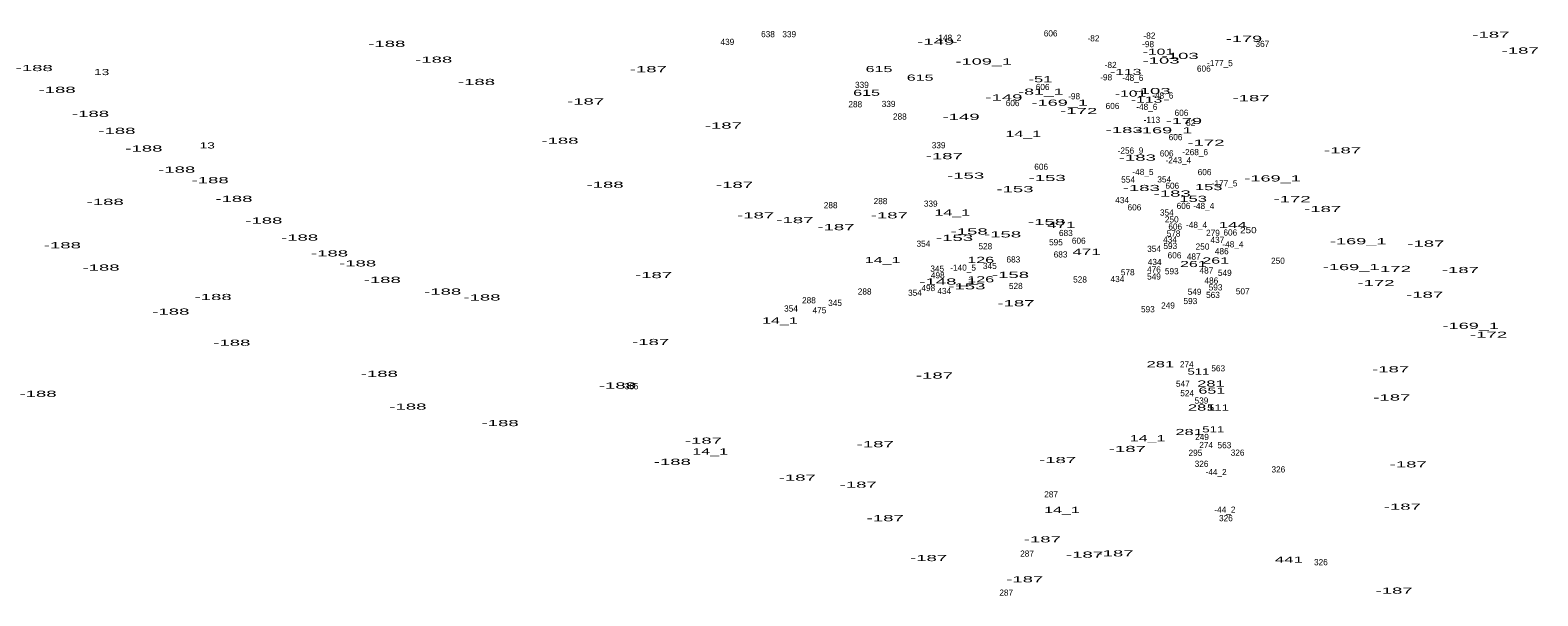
# Model space of a CAD drawing. Extents: x -658595 to -655205, y -1004347 to -1000147.
# Drawn here: x -656433 to -655455, y -1003286 to -1002919 of the extents above; entities that cross this region are included whole.
import ezdxf
from ezdxf.enums import TextEntityAlignment as Align

# ---------------------------------------------------------------- set-up
doc = ezdxf.new("R2010")
doc.units = 0
doc.header["$LTSCALE"] = 1.6
doc.layers.add('24', color=7, linetype='Continuous')

msp = doc.modelspace()

# ---------------------------------------------------------------- texts
at = {"layer": '24'}
for s, p in [('638', (-655954.113, -1002923.98)), ('339', (-655940.333, -1002924.02)), ('606', (-655770.742, -1002923.5)), ('-82', (-655706.665, -1002924.97)), ('439', (-655980.447, -1002929.02)), ('-148_2', (-655837.02, -1002926.35)), ('-82', (-655742.955, -1002926.7)), ('-98', (-655707.53, -1002930.46)), ('367', (-655633.398, -1002930.34)), ('-82', (-655731.815, -1002943.99)), ('-177_5', (-655660.927, -1002942.76)), ('-98', (-655734.7, -1002951.96)), ('-48_6', (-655717.412, -1002952.33)), ('606', (-655671.362, -1002946.34)), ('339', (-655893.173, -1002956.88)), ('606', (-655775.922, -1002958.26)), ('-98', (-655755.53, -1002964.25)), ('-48_6', (-655697.992, -1002963.76)), ('288', (-655897.477, -1002969.41)), ('339', (-655875.863, -1002969.25)), ('606', (-655795.402, -1002968.66)), ('606', (-655730.612, -1002970.55)), ('-48_6', (-655708.362, -1002971.1)), ('288', (-655868.567, -1002977.4)), ('-113', (-655705.071, -1002979.53)), ('606', (-655685.872, -1002974.97)), ('82', (-655679.907, -1002981.41)), ('606', (-655689.712, -1002990.74)), ('339', (-655843.403, -1002996.01)), ('-256_9', (-655718.943, -1002999.45)), ('606', (-655695.472, -1003001.3)), ('-268_6', (-655676.973, -1003000.44)), ('606', (-655776.882, -1003009.93)), ('-243_4', (-655687.891, -1003005.69)), ('554', (-655720.501, -1003018.24)), ('-48_5', (-655710.837, -1003013.33)), ('354', (-655697.071, -1003018.12)), ('606', (-655691.822, -1003022.24)), ('606', (-655670.892, -1003013.4)), ('-177_5', (-655657.887, -1003020.67)), ('288', (-655881.117, -1003032.19)), ('434', (-655724.376, -1003031.54)), ('288', (-655913.447, -1003034.85)), ('339', (-655848.533, -1003033.87)), ('606', (-655716.402, -1003036.26)), ('354', (-655695.361, -1003039.62)), ('606', (-655684.532, -1003035.3)), ('-48_4', (-655671.411, -1003035.34)), ('250', (-655692.171, -1003044.07)), ('606', (-655689.912, -1003048.72)), ('-48_4', (-655676.081, -1003047.62)), ('354', (-655853.261, -1003059.83)), ('528', (-655813.117, -1003061.48)), ('595', (-655767.293, -1003058.89)), ('683', (-655760.873, -1003052.87)), ('606', (-655752.512, -1003057.88)), ('434', (-655693.276, -1003057.12)), ('593', (-655693.123, -1003061.29)), ('578', (-655691.043, -1003053.22)), ('250', (-655672.211, -1003061.68)), ('279', (-655665.438, -1003052.77)), ('437', (-655662.587, -1003057.34)), ('-48_4', (-655652.471, -1003060.19)), ('606', (-655654.192, -1003052.56)), ('683', (-655794.923, -1003070)), ('683', (-655764.303, -1003066.76)), ('354', (-655703.641, -1003063.12)), ('434', (-655703.266, -1003071.67)), ('606', (-655690.392, -1003067.35)), ('487', (-655677.937, -1003068.14)), ('486', (-655659.747, -1003064.67)), ('250', (-655623.281, -1003070.85)), ('345', (-655844.311, -1003075.99)), ('498', (-655843.977, -1003080.29)), ('-140_5', (-655827.524, -1003075.34)), ('345', (-655810.191, -1003074.23)), ('578', (-655720.723, -1003078.34)), ('476', (-655703.713, -1003076.52)), ('549', (-655703.697, -1003081.08)), ('593', (-655692.173, -1003077.66)), ('487', (-655669.687, -1003077.17)), ('549', (-655657.767, -1003078.7)), ('288', (-655891.387, -1003090.79)), ('498', (-655850.107, -1003088.54)), ('434', (-655839.796, -1003090.47)), ('528', (-655793.337, -1003087.21)), ('528', (-655751.667, -1003082.99)), ('434', (-655727.416, -1003082.71)), ('549', (-655677.357, -1003090.97)), ('486', (-655666.467, -1003083.69)), ('593', (-655663.743, -1003088.12)), ('507', (-655646.137, -1003090.67)), ('288', (-655927.527, -1003096.49)), ('345', (-655910.611, -1003098.2)), ('354', (-655858.771, -1003091.6)), ('249', (-655694.597, -1003099.86)), ('593', (-655680.103, -1003096.97)), ('563', (-655665.443, -1003093.02)), ('354', (-655939.181, -1003101.83)), ('475', (-655920.727, -1003102.97)), ('593', (-655707.673, -1003102.29)), ('274', (-655682.397, -1003137.96)), ('563', (-655662.023, -1003140.58)), ('365', (-656042.583, -1003152.2)), ('547', (-655685.007, -1003150.57)), ('524', (-655682.181, -1003156.7)), ('539', (-655672.903, -1003161.5)), ('249', (-655672.537, -1003185.1)), ('295', (-655676.833, -1003195.34)), ('274', (-655669.847, -1003190.28)), ('563', (-655658.033, -1003190.42)), ('326', (-655649.453, -1003195.25)), ('326', (-655672.843, -1003202.48)), ('-44_2', (-655663.401, -1003207.82)), ('326', (-655623.013, -1003206.09)), ('287', (-655770.453, -1003222.25)), ('-44_2', (-655657.691, -1003232.2)), ('326', (-655657.053, -1003237.67)), ('287', (-655786.043, -1003260.68)), ('326', (-655595.433, -1003266.21)), ('287', (-655799.553, -1003285.98))]:
    msp.add_text(s, height=4, dxfattribs=at).set_placement(p, align=Align.CENTER)
for s, width, p in [('-187', 2.25, (-655485.145, -1002924.36)), ('-188', 2.25, (-656201.391, -1002930.25)), ('-149', 2.25, (-655845.381, -1002928.88)), ('-179', 2.2, (-655645.299, -1002927.02)), ('-187', 2.25, (-655466.125, -1002934.63)), ('-188', 2.25, (-656170.961, -1002940.53)), ('-109_1', 2.2, (-655814.109, -1002941.72)), ('-103', 2.25, (-655699.117, -1002941.08)), ('-101', 1.9, (-655700.843, -1002935.41)), ('-103', 2.25, (-655686.727, -1002938.11)), ('-188', 2.25, (-656430.111, -1002945.97)), ('13', 1.65, (-656386.347, -1002948.56)), ('-187', 2.25, (-656031.735, -1002946.71)), ('615', 1.95, (-655882.093, -1002946.62)), ('615', 1.95, (-655855.393, -1002952.19)), ('-51', 2, (-655777.371, -1002953.2)), ('-113', 1.9, (-655722.047, -1002948.51)), ('-188', 2.25, (-656415.271, -1002960.05)), ('-188', 2.25, (-656143.201, -1002954.99)), ('615', 1.95, (-655890.153, -1002961.99)), ('-81_1', 2.15, (-655777.057, -1002961.28)), ('-101', 1.9, (-655718.893, -1002962.49)), ('-103', 2.25, (-655704.967, -1002960.87)), ('-187', 2.25, (-656072.435, -1002967.62)), ('-149', 2.25, (-655801.071, -1002965.03)), ('-169_1', 2.2, (-655764.827, -1002968.42)), ('-172', 2.25, (-655752.555, -1002973.83)), ('-113', 1.9, (-655708.497, -1002966.46)), ('-187', 2.25, (-655640.715, -1002965.45)), ('-188', 2.25, (-656393.591, -1002975.65)), ('-187', 2.25, (-655983.045, -1002983.22)), ('-149', 2.25, (-655828.831, -1002977.59)), ('-179', 2.2, (-655684.289, -1002980.29)), ('-188', 2.25, (-656376.481, -1002986.68)), ('-188', 2.25, (-656089.081, -1002993.06)), ('14_1', 1.95, (-655788.491, -1002988.6)), ('-183', 2.25, (-655723.061, -1002986.13)), ('-169_1', 2.2, (-655697.127, -1002986.3)), ('-188', 2.25, (-656358.981, -1002998.1)), ('13', 1.65, (-656317.877, -1002996.12)), ('-187', 2.25, (-655839.725, -1003003.04)), ('-172', 2.25, (-655670.015, -1002994.38)), ('-187', 2.25, (-655581.375, -1002999.31)), ('-188', 2.25, (-656337.681, -1003011.79)), ('-183', 2.25, (-655714.501, -1003004.02)), ('-188', 2.25, (-656316.001, -1003018.64)), ('-188', 2.25, (-656059.791, -1003021.6)), ('-187', 2.25, (-655975.825, -1003021.67)), ('-153', 2.25, (-655825.871, -1003015.7)), ('-153', 2.25, (-655772.991, -1003017.22)), ('-169_1', 2.2, (-655626.757, -1003017.51)), ('-188', 2.25, (-656384.051, -1003032.72)), ('-188', 2.25, (-656300.561, -1003030.73)), ('-153', 2.25, (-655793.911, -1003024.45)), ('-183', 2.25, (-655711.931, -1003023.71)), ('-183', 2.25, (-655691.871, -1003027.32)), ('153', 2, (-655678.277, -1003030.73)), ('153', 2, (-655668.197, -1003023.12)), ('-172', 2.25, (-655614.095, -1003030.91)), ('-187', 2.25, (-655962.125, -1003041.45)), ('-187', 2.25, (-655875.405, -1003041.45)), ('14_1', 1.95, (-655834.521, -1003039.59)), ('-187', 2.25, (-655594.305, -1003037.33)), ('-188', 2.25, (-656281.161, -1003044.81)), ('-187', 2.25, (-655936.645, -1003044.5)), ('-187', 2.25, (-655910.015, -1003049.06)), ('-158', 2.25, (-655823.611, -1003051.87)), ('-158', 2.25, (-655773.401, -1003045.78)), ('471', 2.05, (-655763.848, -1003047.62)), ('144', 2.05, (-655652.629, -1003047.71)), ('250', 1.2, (-655642.47, -1003051.03)), ('-188', 2.25, (-656411.851, -1003060.83)), ('-188', 2.25, (-656257.961, -1003055.84)), ('-153', 2.25, (-655833.091, -1003056.03)), ('-158', 2.25, (-655801.921, -1003053.77)), ('-169_1', 2.2, (-655571.227, -1003058.22)), ('-187', 2.25, (-655527.365, -1003059.75)), ('-188', 2.25, (-656238.561, -1003066.11)), ('14_1', 1.95, (-655879.781, -1003070.41)), ('126', 1.95, (-655816.113, -1003070.32)), ('471', 2.05, (-655747.438, -1003065.1)), ('261', 1.95, (-655663.673, -1003070.71)), ('-188', 2.25, (-656386.751, -1003075.29)), ('-188', 2.25, (-656220.301, -1003072.58)), ('-187', 2.25, (-656028.315, -1003080.15)), ('-158', 2.25, (-655796.791, -1003080.03)), ('261', 1.95, (-655678.133, -1003072.99)), ('-169_1', 2.2, (-655575.787, -1003074.96)), ('-172', 2.25, (-655549.055, -1003076.19)), ('-187', 2.25, (-655504.925, -1003076.87)), ('-188', 2.25, (-656204.331, -1003083.24)), ('-188', 2.25, (-656165.151, -1003090.85)), ('-148_1', 2.25, (-655837.203, -1003084.32)), ('-153', 2.25, (-655825.101, -1003087.42)), ('126', 1.95, (-655816.113, -1003082.88)), ('-172', 2.25, (-655559.705, -1003085.32)), ('-188', 2.25, (-656314.061, -1003094.36)), ('-188', 2.25, (-656139.661, -1003094.65)), ('-187', 2.25, (-655793.245, -1003098.42)), ('-187', 2.25, (-655528.125, -1003092.89)), ('-188', 2.25, (-656341.481, -1003103.83)), ('14_1', 1.95, (-655946.351, -1003109.6)), ('-169_1', 2.2, (-655498.197, -1003113.01)), ('-172', 2.25, (-655486.675, -1003118.8)), ('-188', 2.25, (-656301.931, -1003123.99)), ('-187', 2.25, (-656030.215, -1003123.53)), ('281', 2, (-655699.557, -1003137.91)), ('-188', 2.25, (-656206.231, -1003144.12)), ('-187', 2.25, (-655846.115, -1003145.23)), ('511', 1.6, (-655674.864, -1003142.69)), ('-187', 2.25, (-655550.185, -1003141.21)), ('-188', 2.25, (-656427.631, -1003157.09)), ('-188', 2.25, (-656051.801, -1003151.73)), ('281', 2, (-655666.757, -1003150.47)), ('651', 1.95, (-655666.173, -1003155.03)), ('-187', 2.25, (-655549.425, -1003159.47)), ('-188', 2.25, (-656187.701, -1003165.4)), ('281', 2, (-655672.747, -1003165.97)), ('511', 1.6, (-655662.194, -1003166.01)), ('-188', 2.25, (-656127.871, -1003176.08)), ('-187', 2.25, (-655995.975, -1003187.46)), ('14_1', 1.95, (-655707.861, -1003185.91)), ('281', 2, (-655680.917, -1003181.86)), ('511', 1.6, (-655665.264, -1003180.14)), ('14_1', 1.95, (-655991.611, -1003194.45)), ('-187', 2.25, (-655884.535, -1003189.74)), ('-187', 2.25, (-655720.975, -1003192.84)), ('-188', 2.25, (-656016.161, -1003201.17)), ('-187', 2.25, (-655766.235, -1003200.02)), ('-187', 2.25, (-655538.775, -1003202.85)), ('-187', 2.25, (-655935.115, -1003211.43)), ('-187', 2.25, (-655895.565, -1003216)), ('-187', 2.25, (-655878.065, -1003237.69)), ('14_1', 1.95, (-655763.391, -1003232.33)), ('-187', 2.25, (-655542.585, -1003230.25)), ('-187', 2.25, (-655776.125, -1003251.43)), ('-187', 2.25, (-655849.915, -1003263.56)), ('-187', 2.25, (-655748.745, -1003261.33)), ('-187', 2.25, (-655728.965, -1003260.51)), ('441', 2.05, (-655616.189, -1003264.59)), ('-187', 2.25, (-655787.535, -1003277.31)), ('-187', 2.25, (-655547.905, -1003284.66))]:
    msp.add_text(s, height=4, dxfattribs=dict(at, width=width)).set_placement(p, align=Align.CENTER)

doc.saveas('drawing.dxf')
